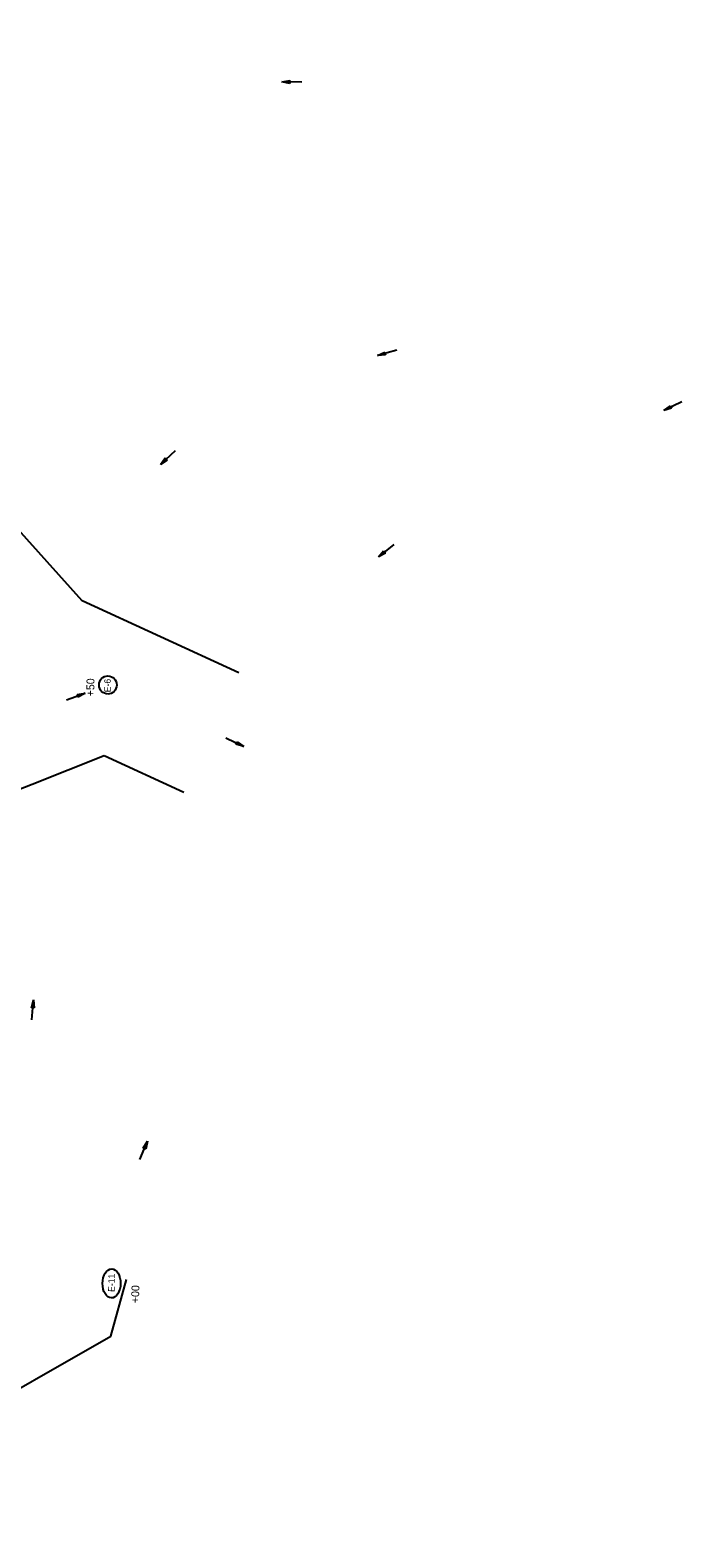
# Model space of a CAD drawing. Extents: x 1312891 to 1314734, y 2088044 to 2090982.
# Drawn here: x 1314240 to 1314734, y 2088270 to 2089414 of the extents above; entities that cross this region are included whole.
import ezdxf

# ---------------------------------------------------------------- set-up
doc = ezdxf.new("R2010")
doc.units = 0
for name, color, linetype in [('43', 7, 'Continuous'), ('44', 7, 'Continuous'), ('Level 1', 7, 'Continuous'), ('Level 44', 7, 'Continuous'), ('R_Buffer', 7, 'Continuous')]:
    doc.layers.add(name, color=color, linetype=linetype)

msp = doc.modelspace()

# ---------------------------------------------------------------- linework, layer by layer
at = {"layer": '43'}
for p, q in [((1314430.7, 2089374.9), (1314436.8, 2089375.9)), ((1314436.8, 2089373.7), (1314430.7, 2089374.9)), ((1314436.8, 2089375.9), (1314436.8, 2089373.7)), ((1314503.1, 2089167.2), (1314508.7, 2089169.8)), ((1314508.7, 2089169.8), (1314509.3, 2089167.7)), ((1314509.3, 2089167.7), (1314503.1, 2089167.2)), ((1314720.5, 2089125.5), (1314725.5, 2089129)), ((1314726.4, 2089127.1), (1314720.5, 2089125.5)), ((1314725.5, 2089129), (1314726.4, 2089127.1)), ((1314338.6, 2089084.4), (1314342.2, 2089089.4)), ((1314343.7, 2089087.8), (1314338.6, 2089084.4)), ((1314342.2, 2089089.4), (1314343.7, 2089087.8)), ((1314503.9, 2089014.3), (1314507.9, 2089018.9)), ((1314509.3, 2089017.2), (1314503.9, 2089014.3)), ((1314507.9, 2089018.9), (1314509.3, 2089017.2)), ((1314275.3, 2088909.9), (1314281.4, 2088910.9)), ((1314276.1, 2088907.8), (1314275.3, 2088909.9)), ((1314281.4, 2088910.9), (1314276.1, 2088907.8)), ((1314395.8, 2088872.1), (1314396.8, 2088874)), ((1314401.8, 2088870.4), (1314395.8, 2088872.1)), ((1314396.8, 2088874), (1314401.8, 2088870.4)), ((1314240.6, 2088672.1), (1314242.2, 2088678.1)), ((1314242.2, 2088678.1), (1314242.7, 2088672)), ((1314242.7, 2088672), (1314240.6, 2088672.1)), ((1314325.4, 2088565.7), (1314328.8, 2088570.9)), ((1314327.4, 2088564.9), (1314325.4, 2088565.7)), ((1314328.8, 2088570.9), (1314327.4, 2088564.9))]:
    msp.add_line(p, q, dxfattribs=at)
for points in [[(1314445.9, 2089374.7), (1314430.7, 2089374.9)], [(1314517.8, 2089171.2), (1314503.1, 2089167.2)], [(1314734.2, 2089132), (1314720.5, 2089125.5)], [(1314349.6, 2089094.8), (1314338.6, 2089084.4)], [(1314515.7, 2089023.8), (1314503.9, 2089014.3)], [(1314267.1, 2088905.8), (1314281.4, 2088910.9)], [(1314388.1, 2088877), (1314401.8, 2088870.4)], [(1314240.8, 2088663), (1314242.2, 2088678.1)], [(1314322.8, 2088557), (1314328.8, 2088570.9)]]:
    msp.add_lwpolyline(points, dxfattribs=at)
at = {"layer": 'Level 1'}
for centre, major_axis, ratio in [((1314298.6, 2088917.1), (-0.05, -6.88), 0.97521), ((1314301.4, 2088462.9), (0.1, 11), 0.622952)]:
    msp.add_ellipse(centre, major_axis=major_axis, ratio=ratio, dxfattribs=at)
at = {"layer": 'Level 44'}
msp.add_lwpolyline([(1314039.6, 2088269.8), (1314089.5, 2088339.8), (1314183.1, 2088355.6), (1314300.8, 2088423), (1314312.7, 2088465.9)], dxfattribs=at)
at = {"layer": 'R_Buffer'}
for points in [[(1314398.1, 2088926.4), (1314279.1, 2088981), (1314219.3, 2089047.5), (1314174.9, 2089087.2), (1314129, 2089112), (1314090.9, 2089118.4), (1313947.3, 2089119.9), (1313951.5, 2089132.9), (1313959.5, 2089171.9), (1313955.9, 2089247.9), (1313958.3, 2089279.9), (1313950.4, 2089321.3), (1313950, 2089362.1), (1313946.1, 2089439.7), (1313939.4, 2089474.8), (1313935.3, 2089518.7), (1313906.3, 2089564.9), (1313890.9, 2089585.6), (1313842.8, 2089656.5), (1313803.2, 2089711.6), (1313763.9, 2089776.4), (1313748.1, 2089794.9), (1313663.5, 2089824.2)], [(1314295.9, 2088863.3), (1314241.1, 2088841.7), (1314158.6, 2088809.4), (1314144.1, 2088804), (1314096.9, 2088781.4), (1314059.9, 2088769.2), (1313914.7, 2088770.5), (1313773.6, 2088787.8), (1313618.2, 2088803.5)], [(1314356.3, 2088835.5), (1314295.9, 2088863.3)]]:
    msp.add_lwpolyline(points, dxfattribs=at)

# ---------------------------------------------------------------- texts
at = {"layer": '44'}
for s, rotation, p in [('+50', 89.5, (1314288.3, 2088908.5)), ('+00', 88.324, (1314322.2, 2088447.9))]:
    msp.add_text(s, height=6, rotation=rotation, dxfattribs=at).set_placement(p)
at = {"layer": 'Level 1'}
for s, rotation, p in [('E-6 ', 89.558, (1314300.7, 2088911.6)), ('E-11 ', 89.5, (1314303.7, 2088456.5))]:
    msp.add_text(s, height=4.88, rotation=rotation, dxfattribs=at).set_placement(p)

doc.saveas('drawing.dxf')
